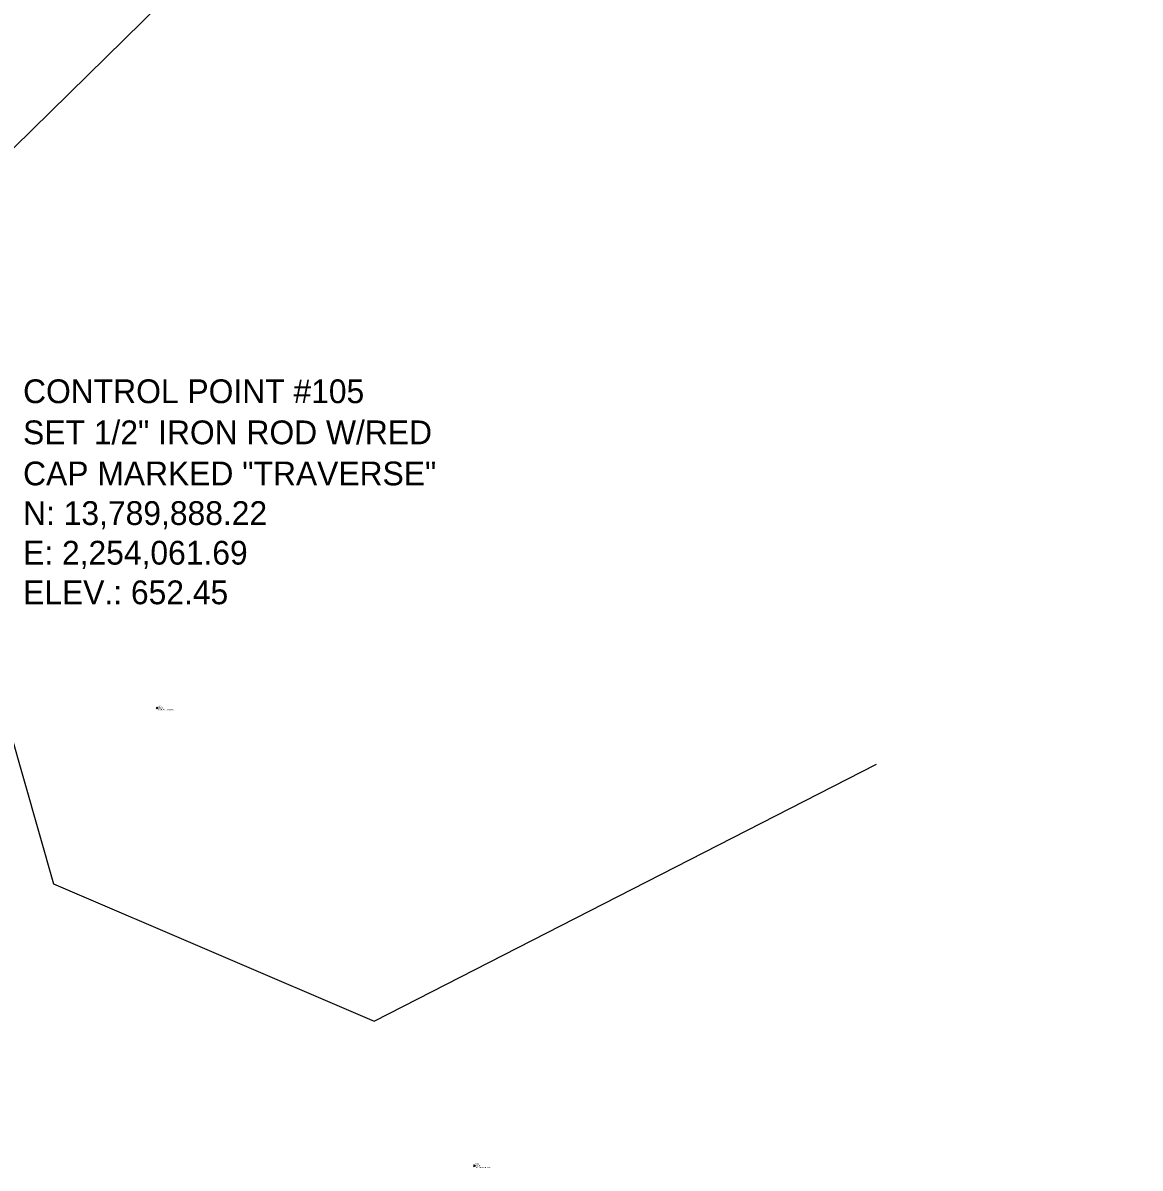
# Model space of a CAD drawing. Extents: x 2250985 to 2256614, y 13788366 to 13792478.
# Drawn here: x 2254074 to 2254130.3, y 13789837.1 to 13789894.9 of the extents above; entities that cross this region are included whole.
import ezdxf

# ---------------------------------------------------------------- set-up
doc = ezdxf.new("R2010")
doc.units = 0
for name, color, linetype in [('BORD_legend_int', 7, 'Continuous'), ('BORD_legend_plan_prof_screen', 7, 'Continuous'), ('BORD_legend_TCP', 7, 'Continuous'), ('BORD_legend_TCP_screen', 7, 'Continuous'), ('E_ROW_Driveway_3D_R', 7, 'Continuous'), ('E_Traf_LightPole', 7, 'Continuous'), ('E_Util_SanManhole', 7, 'Continuous')]:
    doc.layers.add(name, color=color, linetype=linetype)

# ---------------------------------------------------------------- blocks, each defined once
blk = doc.blocks.new('NG')
at = {"layer": 'BORD_legend_plan_prof_screen'}
for p in [(-0.07, 0.09), (-0.07, -0.09), (0.07, 0.09), (0.07, -0.09)]:
    blk.add_line(p, (0, 0), dxfattribs=at)

msp = doc.modelspace()

# ---------------------------------------------------------------- linework, layer by layer
at = {"layer": 'E_ROW_Driveway_3D_R'}
msp.add_lwpolyline([(2254057.29, 13789871.24), (2254063.29, 13789878.54), (2254111.58, 13789925.98), (2254185.81, 13790003.22), (2254253.26, 13790074.98)], dxfattribs=at)
at = {"layer": 'E_Util_SanManhole'}
msp.add_lwpolyline([(2254074.597, 13789918.655), (2254062.801, 13789903.734), (2254050.463, 13789889.665), (2254051.525, 13789884.105), (2254061.34, 13789880.062), (2254067.982, 13789885.201), (2254073.051, 13789888.129), (2254070.725, 13789885.209), (2254068.642, 13789877.573), (2254068.121, 13789873.083), (2254071.774, 13789864.483), (2254075.516, 13789851.421), (2254091.687, 13789844.495), (2254117.025, 13789857.458)], dxfattribs=at)

# ---------------------------------------------------------------- block references
at = {"layer": 'BORD_legend_plan_prof_screen', "xscale": 0.5, "yscale": 0.5}
for p in [(2254080.74, 13789860.3), (2254096.74, 13789837.2)]:
    msp.add_blockref('NG', p, dxfattribs=at)

# ---------------------------------------------------------------- texts
at = {"layer": 'BORD_legend_int'}
for p in [(2254080.8, 13789860.18), (2254096.8, 13789837.08)]:
    msp.add_text('NATURAL GROUND', height=0.06, dxfattribs=at).set_placement(p)
at = {"layer": 'BORD_legend_TCP'}
for s, p in [('6375', (2254080.8, 13789860.36)), ('6700', (2254096.8, 13789837.26))]:
    msp.add_text(s, height=0.06, dxfattribs=at).set_placement(p)
at = {"layer": 'BORD_legend_TCP_screen'}
for s, p in [('652.61', (2254080.8, 13789860.27)), ('653.18', (2254096.8, 13789837.17))]:
    msp.add_text(s, height=0.06, dxfattribs=at).set_placement(p)
at = {"layer": 'E_Traf_LightPole'}
for s, p in [('CONTROL POINT #105', (2254073.975, 13789875.683)), ('SET 1/2" IRON ROD W/RED ', (2254073.975, 13789873.609)), ('CAP MARKED "TRAVERSE"', (2254073.975, 13789871.535)), ('N: 13,789,888.22', (2254073.975, 13789869.535)), ('E: 2,254,061.69', (2254073.975, 13789867.535)), ('ELEV.: 652.45', (2254073.975, 13789865.535))]:
    msp.add_text(s, height=1.2, dxfattribs=at).set_placement(p)

doc.saveas('drawing.dxf')
